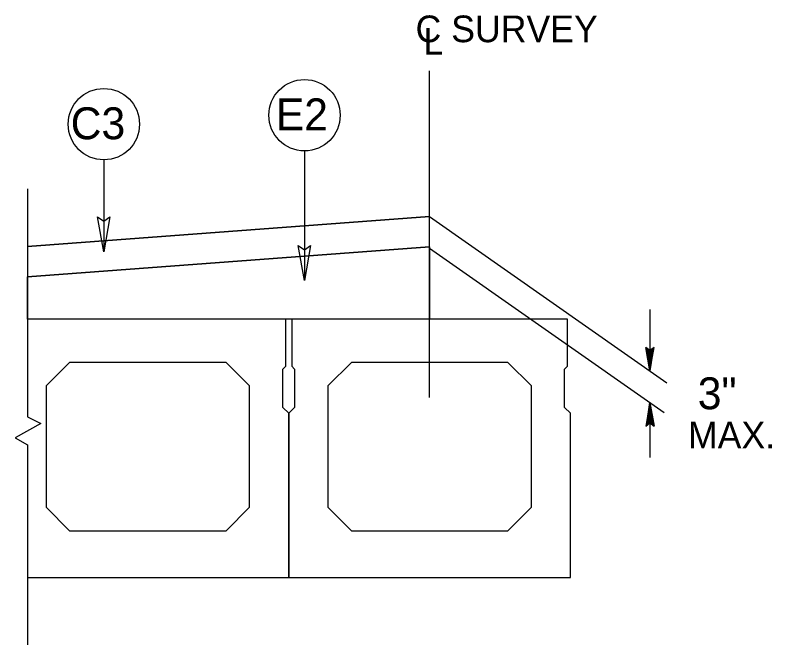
# Model space of a CAD drawing. Extents: x 573711 to 575883, y -54585 to -53485.
# Drawn here: x 575695.3 to 575882.9, y -54477.4 to -54321.3 of the extents above; entities that cross this region are included whole.
import ezdxf

# ---------------------------------------------------------------- set-up
doc = ezdxf.new("R2010")
doc.units = 0
for name, color, linetype in [('Old_Level_1', 7, 'Continuous'), ('Old_Level_11', 7, 'Continuous'), ('Old_Level_20', 7, 'Continuous'), ('Old_Level_21', 7, 'Continuous'), ('Prop Dimension Text', 7, 'Continuous'), ('Prop Shade Medium', 7, 'Continuous')]:
    doc.layers.add(name, color=color, linetype=linetype)

msp = doc.modelspace()

# ---------------------------------------------------------------- linework, layer by layer
at = {"layer": 'Old_Level_1'}
for p, q in [((575798.08, -54416.06), (575798.09, -54335.15)), ((575698.35, -54364.33), (575698.35, -54420.86)), ((575698.35, -54378.64), (575798.09, -54371.22)), ((575798.09, -54371.22), (575856.9, -54412.42)), ((575798.09, -54378.72), (575698.35, -54386.14)), ((575798.09, -54379.09), (575856.26, -54419.83)), ((575852.71, -54394.27), (575852.7, -54409.47)), ((575852.7, -54409.47), (575851.68, -54403.65)), ((575852.71, -54404.41), (575851.68, -54403.65)), ((575852.7, -54409.47), (575851.83, -54403.76)), ((575851.97, -54403.87), (575852.7, -54409.47)), ((575852.7, -54409.47), (575852.12, -54403.98)), ((575852.26, -54404.09), (575852.7, -54409.47)), ((575852.7, -54409.47), (575852.41, -54404.19)), ((575852.55, -54404.3), (575852.7, -54409.47)), ((575852.7, -54409.47), (575853.73, -54403.65)), ((575853.58, -54403.76), (575852.7, -54409.47)), ((575852.7, -54409.47), (575853.43, -54403.87)), ((575853.29, -54403.98), (575852.7, -54409.47)), ((575852.7, -54409.47), (575853.14, -54404.09)), ((575853, -54404.19), (575852.7, -54409.47)), ((575852.7, -54409.47), (575852.85, -54404.3)), ((575852.71, -54404.41), (575852.7, -54409.47)), ((575853.73, -54403.65), (575852.71, -54404.41)), ((575852.7, -54417.34), (575851.68, -54423.16)), ((575851.82, -54423.04), (575852.7, -54417.34)), ((575852.7, -54417.34), (575851.97, -54422.94)), ((575852.11, -54422.82), (575852.7, -54417.34)), ((575852.7, -54417.34), (575852.26, -54422.72)), ((575852.4, -54422.62), (575852.7, -54417.34)), ((575852.7, -54417.34), (575852.55, -54422.51)), ((575852.7, -54417.34), (575852.7, -54430.94)), ((575852.7, -54417.34), (575853.73, -54423.16)), ((575852.7, -54422.4), (575852.7, -54417.34)), ((575852.85, -54422.51), (575852.7, -54417.34)), ((575852.7, -54417.34), (575852.99, -54422.62)), ((575853.14, -54422.72), (575852.7, -54417.34)), ((575852.7, -54417.34), (575853.28, -54422.82)), ((575853.43, -54422.94), (575852.7, -54417.34)), ((575852.7, -54417.34), (575853.58, -54423.04)), ((575851.68, -54423.16), (575852.7, -54422.4)), ((575852.7, -54422.4), (575853.73, -54423.16)), ((575698.35, -54427.84), (575698.35, -54477.39))]:
    msp.add_line(p, q, dxfattribs=at)
msp.add_lwpolyline([(575698.35, -54420.86), (575701.72, -54422.54), (575695.32, -54426.04), (575698.35, -54427.84)], dxfattribs=at)
at = {"layer": 'Old_Level_11'}
for p, q in [((575767.07, -54354.95), (575767.07, -54387.11)), ((575717.32, -54357.17), (575717.32, -54380.01))]:
    msp.add_line(p, q, dxfattribs=at)
for points in [[(575698.35, -54386.14), (575798.09, -54378.72), (575798.09, -54371.22), (575698.35, -54378.64)], [(575718.82, -54371.32), (575717.32, -54380.01), (575715.77, -54371.27), (575717.32, -54372.38)], [(575698.35, -54386.14), (575798.09, -54378.72), (575798.08, -54396.7), (575698.35, -54396.7)], [(575768.56, -54378.43), (575767.07, -54387.11), (575765.52, -54378.38), (575767.07, -54379.49)]]:
    msp.add_lwpolyline(points, close=True, dxfattribs=at)
for centre in [(575767.07, -54346.12), (575717.32, -54348.34)]:
    msp.add_circle(centre, 8.84, dxfattribs=at)
at = {"layer": 'Prop Dimension Text'}
for p, q in [((575762.43, -54396.7), (575698.35, -54396.7)), ((575762.43, -54408.34), (575762.43, -54396.7)), ((575761.71, -54409.07), (575762.43, -54408.34)), ((575761.71, -54418.53), (575761.71, -54409.07)), ((575763.16, -54419.98), (575761.71, -54418.53)), ((575763.16, -54460.73), (575763.16, -54419.98)), ((575698.35, -54460.73), (575763.16, -54460.73))]:
    msp.add_line(p, q, dxfattribs=at)
for points in [[(575833.01, -54460.73), (575833.01, -54419.98), (575831.55, -54418.53), (575831.55, -54409.07), (575832.28, -54408.34), (575832.28, -54396.7), (575763.89, -54396.7), (575763.89, -54408.34), (575764.62, -54409.07), (575764.62, -54418.53), (575763.16, -54419.98), (575763.16, -54460.73)], [(575747.64, -54449.09), (575753.46, -54443.27), (575753.46, -54413.2), (575747.64, -54407.37), (575708.83, -54407.37), (575703.01, -54413.2), (575703.01, -54443.27), (575708.83, -54449.09)], [(575817.49, -54449.09), (575823.31, -54443.27), (575823.31, -54413.2), (575817.49, -54407.37), (575778.68, -54407.37), (575772.86, -54413.2), (575772.86, -54443.27), (575778.68, -54449.09)]]:
    msp.add_lwpolyline(points, close=True, dxfattribs=at)
at = {"layer": 'Prop Shade Medium'}
msp.add_line((575698.35, -54386.14), (575798.09, -54378.72), dxfattribs=at)
for points in [[(575798.09, -54371.22), (575698.35, -54378.64), (575698.35, -54386.14)], [(575798.09, -54378.72), (575798.09, -54378.72), (575798.09, -54371.22)]]:
    msp.add_lwpolyline(points, dxfattribs=at)

# ---------------------------------------------------------------- texts
at = {"layer": 'Old_Level_1'}
for s, height, p in [('C SURVEY ', 6.609, (575794.6, -54328.02)), ('L', 6.61, (575796.53, -54331.11))]:
    msp.add_text(s, height=height, rotation=359.9946, dxfattribs=at).set_placement(p)
at = {"layer": 'Old_Level_20'}
for s, p in [('E2', (575759.94, -54349.86)), ('C3', (575709.1, -54352.07)), ('3"', (575864.57, -54418.99))]:
    msp.add_text(s, height=7.908, rotation=359.9946, dxfattribs=at).set_placement(p)
at = {"layer": 'Old_Level_21'}
msp.add_text('MAX.', height=6.609, rotation=359.9946, dxfattribs=at).set_placement((575862.14, -54428.71))

doc.saveas('drawing.dxf')
